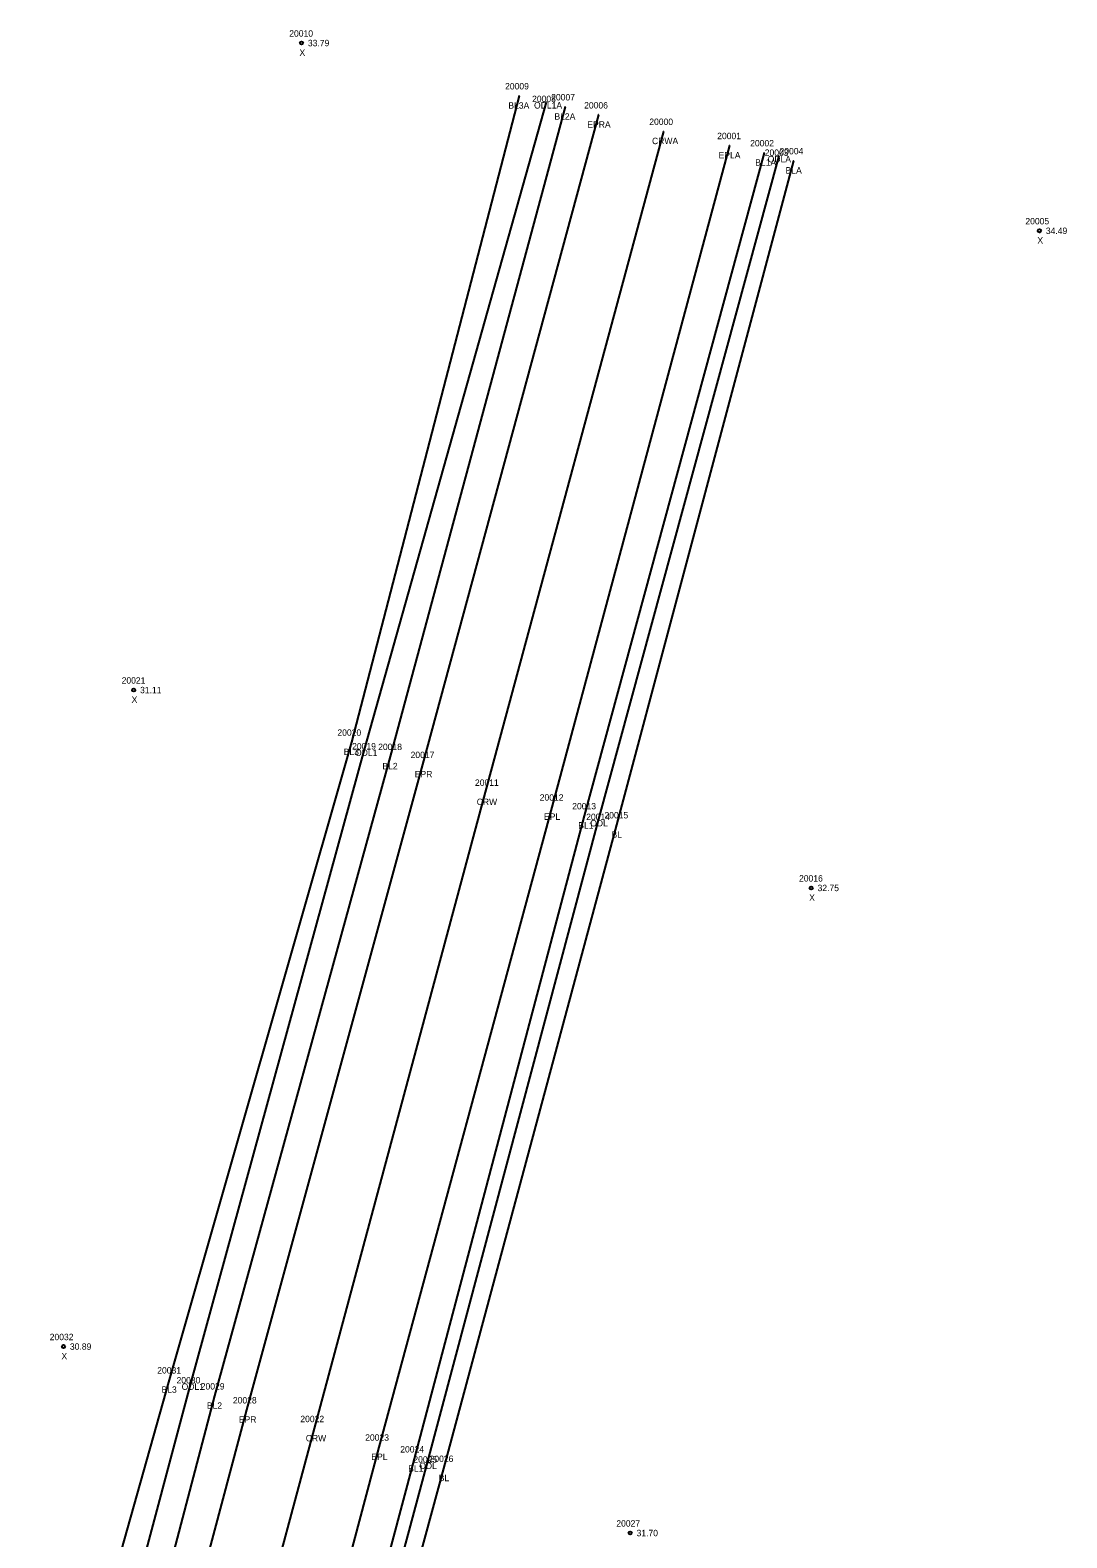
# Model space of a CAD drawing. Extents: x 2432729 to 2433340, y 684958 to 688103.
# Drawn here: x 2433041.9 to 2433203.8, y 687867.9 to 688103.5 of the extents above; entities that cross this region are included whole.
import ezdxf

# ---------------------------------------------------------------- set-up
doc = ezdxf.new("R2010")
doc.units = 0
for name, color, linetype in [('RD_DTM_BkLn1', 7, 'Continuous'), ('RD_EX_H2O', 7, 'Continuous'), ('RD_EX_H2O_txCode', 7, 'Continuous'), ('RD_EX_Road', 7, 'Continuous'), ('RD_EX_Road_txCode', 7, 'Continuous'), ('RD_Sketch8', 7, 'Continuous'), ('RD_SMD_Locator', 7, 'Continuous'), ('RD_SMD_Misc', 7, 'Continuous')]:
    doc.layers.add(name, color=color, linetype=linetype)

msp = doc.modelspace()

# ---------------------------------------------------------------- linework, layer by layer
at = {"layer": 'RD_DTM_BkLn1'}
for points in [[(2433118.26, 688093.2), (2433092.06, 687992.21), (2433063.59, 687892.57), (2433035.4, 687792.67), (2433003.26, 687693.63), (2432973.78, 687591.87), (2432942.45, 687477.63), (2432922.14, 687395), (2432910.39, 687336.67), (2432899.1, 687275.13), (2432892.65, 687218), (2432891.75, 687172.49)], [(2433125.46, 688091.48), (2433098.1, 687989.98), (2433070.67, 687890.07), (2433044.57, 687790.6), (2433009.89, 687691.98), (2432980.82, 687589.28), (2432951.34, 687483.95), (2432927.37, 687394.4), (2432914.6, 687336.1), (2432907.58, 687275.27), (2432904.68, 687217.27), (2432900.37, 687172.96), (2432891.75, 687172.49)], [(2433140.82, 688087.65), (2433112.94, 687984.39), (2433086.23, 687884.97), (2433060.15, 687787.81), (2433032.83, 687687.07), (2433004.93, 687584.9), (2432976.21, 687475.71), (2432953.67, 687387.58), (2432941.78, 687332.31), (2432932.37, 687274.14), (2432926.02, 687213.66), (2432924.35, 687158.94)], [(2433156.54, 688084.3), (2433128.42, 687980.72), (2433101.84, 687880.23), (2433076.15, 687783.58), (2433056.79, 687706.65), (2433053.61, 687680.85), (2433043.6, 687649.71), (2433027.96, 687578.58), (2432999.4, 687470.47), (2432976.82, 687380.76), (2432967.08, 687327.52), (2432956.82, 687270.44), (2432953.12, 687234.52), (2432952.13, 687211.69)], [(2433161.14, 688083.06), (2433133.45, 687979.3), (2433106.44, 687878.75), (2433080.34, 687782.58), (2433063.71, 687704.97), (2433062.78, 687678.91), (2433051.75, 687646.46), (2433035.42, 687577.73), (2433004.6, 687469.86), (2432982.67, 687378.73), (2432971.98, 687326.06), (2432962.83, 687268.71), (2432961.78, 687241.18), (2432987.4, 687248.62)]]:
    msp.add_lwpolyline(points, dxfattribs=at)
at = {"layer": 'RD_EX_H2O'}
for points in [[(2433122.48, 688092.22), (2433094.03, 687991.07), (2433066.93, 687892.02), (2433040.1, 687791.41), (2433006.23, 687692.29), (2432977.32, 687590.19), (2432946.52, 687480.52), (2432925.1, 687394.47), (2432912.11, 687336.21), (2432903.51, 687275.66), (2432898.99, 687217.48), (2432895.84, 687179.01)], [(2433158.82, 688083.82), (2433130.6, 687980.05), (2433103.89, 687879.65), (2433077.93, 687783.05), (2433058.91, 687706.24), (2433056.32, 687679.85), (2433046.3, 687648.55), (2433031.84, 687578.12), (2433002.04, 687470.32), (2432979.46, 687380.11), (2432969.67, 687326.76), (2432959.16, 687269.46), (2432956.03, 687234.5)]]:
    msp.add_lwpolyline(points, dxfattribs=at)
at = {"layer": 'RD_EX_Road'}
for points in [[(2433130.63, 688090.22), (2433103.18, 687988.73), (2433075.68, 687887.89), (2433049.83, 687790.75), (2433022.33, 687689.17), (2432994.76, 687586.82), (2432966.23, 687480.17), (2432943.15, 687390.42), (2432931.4, 687334.3), (2432921.83, 687273.88), (2432915.64, 687215.4), (2432913.86, 687159.12)], [(2433151.11, 688085.43), (2433123.35, 687982.08), (2433096.36, 687882.07), (2433070.62, 687785.25), (2433042.64, 687684.31), (2433015.24, 687582.49), (2432986.34, 687474.01), (2432964, 687384.38), (2432952.4, 687330.76), (2432943.09, 687273.42), (2432937.12, 687213.43), (2432935.51, 687158.7)]]:
    msp.add_lwpolyline(points, dxfattribs=at)
at = {"layer": 'RD_SMD_Locator'}
for centre, radius in [((2433084.25, 688101.45), 0.25), ((2433118.26, 688093.2), 0.001), ((2433122.48, 688092.22), 0.001), ((2433125.46, 688091.48), 0.001), ((2433130.63, 688090.22), 0.001), ((2433140.82, 688087.65), 0.001), ((2433151.11, 688085.43), 0.001), ((2433156.54, 688084.3), 0.001), ((2433158.82, 688083.82), 0.001), ((2433161.14, 688083.06), 0.001), ((2433199.55, 688072.12), 0.25), ((2433058.03, 688000.36), 0.25), ((2433092.06, 687992.21), 0.001), ((2433094.03, 687991.07), 0.001), ((2433098.1, 687989.98), 0.001), ((2433103.18, 687988.73), 0.001), ((2433112.94, 687984.39), 0.001), ((2433123.35, 687982.08), 0.001), ((2433128.42, 687980.72), 0.001), ((2433130.6, 687980.05), 0.001), ((2433133.45, 687979.3), 0.001), ((2433163.88, 687969.44), 0.25), ((2433047.07, 687897.78), 0.25), ((2433063.59, 687892.57), 0.001), ((2433066.93, 687892.02), 0.001), ((2433070.67, 687890.07), 0.001), ((2433075.68, 687887.89), 0.001), ((2433086.23, 687884.97), 0.001), ((2433096.36, 687882.07), 0.001), ((2433101.84, 687880.23), 0.001), ((2433103.89, 687879.65), 0.001), ((2433106.44, 687878.75), 0.001), ((2433135.6, 687868.65), 0.25)]:
    msp.add_circle(centre, radius, dxfattribs=at)

# ---------------------------------------------------------------- texts
at = {"layer": 'RD_EX_H2O_txCode'}
for s, p in [('20008', (2433120.28, 688092.22)), ('ODL1A', (2433120.58, 688091.22)), ('20003', (2433156.63, 688083.82)), ('ODLA', (2433157.09, 688082.82)), ('20019', (2433092.16, 687991.07)), ('ODL1', (2433092.62, 687990.07)), ('20014', (2433128.73, 687980.05)), ('ODL', (2433129.36, 687979.05)), ('20030', (2433064.73, 687892.02)), ('ODL1', (2433065.52, 687891.02)), ('20025', (2433101.73, 687879.65)), ('ODL', (2433102.65, 687878.65))]:
    msp.add_text(s, height=1, dxfattribs=at).set_placement(p)
at = {"layer": 'RD_EX_Road_txCode'}
for s, p in [('20006', (2433128.41, 688091.22)), ('EPRA', (2433128.91, 688088.22)), ('20001', (2433149.2, 688086.43)), ('EPLA', (2433149.42, 688083.43)), ('20017', (2433101.3, 687989.73)), ('EPR', (2433101.95, 687986.73)), ('20012', (2433121.47, 687983.08)), ('EPL', (2433122.14, 687980.08)), ('20028', (2433073.53, 687888.89)), ('EPR', (2433074.46, 687885.89)), ('20023', (2433094.2, 687883.07)), ('EPL', (2433095.16, 687880.07))]:
    msp.add_text(s, height=1, dxfattribs=at).set_placement(p)
at = {"layer": 'RD_Sketch8'}
for s, p in [('20010', (2433082.34, 688102.45)), ('33.79', (2433085.25, 688100.95)), ('X', (2433083.94, 688099.45)), ('20005', (2433197.35, 688073.12)), ('34.49', (2433200.55, 688071.62)), ('X', (2433199.23, 688070.12)), ('20021', (2433056.15, 688001.36)), ('X', (2433057.71, 687998.36)), ('31.11', (2433059.03, 687999.86)), ('20016', (2433161.99, 687970.44)), ('32.75', (2433164.88, 687968.94)), ('X', (2433163.57, 687967.44)), ('20032', (2433044.91, 687898.78)), ('30.89', (2433048.07, 687897.28)), ('X', (2433046.75, 687895.78)), ('20027', (2433133.44, 687869.65)), ('31.70', (2433136.6, 687868.15))]:
    msp.add_text(s, height=1, dxfattribs=at).set_placement(p)
at = {"layer": 'RD_SMD_Misc'}
for s, p in [('20009', (2433116.06, 688094.2)), ('BL3A', (2433116.57, 688091.2)), ('20007', (2433123.26, 688092.48)), ('BL2A', (2433123.77, 688089.48)), ('20000', (2433138.59, 688088.65)), ('CRWA', (2433139.02, 688085.65)), ('20002', (2433154.35, 688085.3)), ('20004', (2433158.94, 688084.06)), ('BL1A', (2433155.14, 688082.3)), ('BLA', (2433159.89, 688081.06)), ('20020', (2433089.86, 687993.21)), ('BL3', (2433090.85, 687990.21)), ('20018', (2433096.23, 687990.98)), ('BL2', (2433096.89, 687987.98)), ('20011', (2433111.35, 687985.39)), ('CRW', (2433111.63, 687982.39)), ('20013', (2433126.55, 687981.72)), ('20015', (2433131.58, 687980.3)), ('BL1', (2433127.5, 687978.72)), ('BL', (2433132.69, 687977.3)), ('20031', (2433061.71, 687893.57)), ('BL3', (2433062.38, 687890.57)), ('20029', (2433068.51, 687891.07)), ('BL2', (2433069.46, 687888.07)), ('20022', (2433084.07, 687885.97)), ('CRW', (2433084.92, 687882.97)), ('20024', (2433099.68, 687881.23)), ('BL1', (2433100.92, 687878.23)), ('20026', (2433104.26, 687879.75)), ('BL', (2433105.69, 687876.75))]:
    msp.add_text(s, height=1, dxfattribs=at).set_placement(p)

doc.saveas('drawing.dxf')
